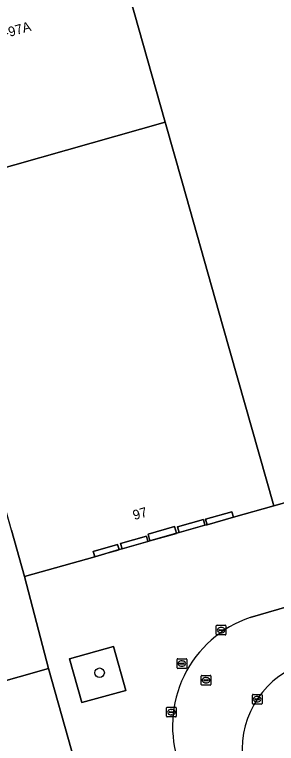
# Model space of a CAD drawing. Extents: x 159680 to 160786, y 387323 to 388340.
# Drawn here: x 159778.2 to 159805.3, y 388088.3 to 388163.8 of the extents above; entities that cross this region are included whole.
import ezdxf

# ---------------------------------------------------------------- set-up
doc = ezdxf.new("R2010")
doc.units = 0
for name, color, linetype in [('IMGEO_Boom', 7, 'Continuous'), ('IMGEO_Erf', 7, 'Continuous'), ('IMGEO_Groenvoorziening', 7, 'Continuous'), ('IMGEO_Kolk', 7, 'Continuous'), ('IMGEO_Pand', 7, 'Continuous'), ('IMGEO_Pand_nummerreeks', 7, 'Continuous'), ('IMGEO_Pand_overbouw', 7, 'Continuous'), ('IMGEO_Rijbaan_lokaal_gesloten', 7, 'Continuous'), ('IMGEO_Rioolput', 7, 'Continuous'), ('IMGEO_Voetpad_open', 7, 'Continuous')]:
    doc.layers.add(name, color=color, linetype=linetype)

msp = doc.modelspace()

# ---------------------------------------------------------------- linework, layer by layer
at = {"layer": 'IMGEO_Boom'}
msp.add_circle((159787.039, 388095.61), 0.489, dxfattribs=at)
at = {"layer": 'IMGEO_Erf'}
msp.add_lwpolyline([(159779.267, 388105.564), (159777.907, 388110.376), (159775.062, 388120.447), (159751.863, 388113.893), (159752.702, 388110.923), (159752.877, 388110.972), (159757.31, 388095.283), (159762.15, 388096.648), (159763.767, 388090.921), (159781.751, 388096.038)], close=True, dxfattribs=at)
at = {"layer": 'IMGEO_Groenvoorziening'}
msp.add_lwpolyline([(159788.459, 388098.325), (159783.926, 388097.046), (159785.198, 388092.511), (159789.733, 388093.783)], close=True, dxfattribs=at)
msp.add_arc((159811.11, 388087.728), 9.316, 111.33818, 189.99653, dxfattribs=at)
at = {"layer": 'IMGEO_Kolk'}
for p, q in [((159799.105, 388099.596), (159799.105, 388100.448)), ((159799.18, 388100.522), (159800.032, 388100.522)), ((159799.593, 388100.302), (159799.618, 388100.302)), ((159800.106, 388100.448), (159800.106, 388099.596)), ((159800.032, 388099.522), (159799.18, 388099.522)), ((159799.364, 388100.016), (159799.364, 388100.028)), ((159799.802, 388099.979), (159799.404, 388099.979)), ((159799.407, 388100.065), (159799.805, 388100.065)), ((159799.616, 388099.742), (159799.591, 388099.742)), ((159799.848, 388100.028), (159799.848, 388100.016)), ((159802.909, 388093.361), (159803.761, 388093.361)), ((159802.834, 388092.435), (159802.834, 388093.287)), ((159803.093, 388092.855), (159803.093, 388092.867)), ((159803.531, 388092.818), (159803.133, 388092.818)), ((159803.136, 388092.904), (159803.534, 388092.904)), ((159803.322, 388093.141), (159803.347, 388093.141)), ((159803.577, 388092.867), (159803.577, 388092.855)), ((159803.835, 388093.287), (159803.835, 388092.435)), ((159793.964, 388091.104), (159793.964, 388091.956)), ((159794.039, 388092.03), (159794.891, 388092.03)), ((159794.965, 388091.956), (159794.965, 388091.104)), ((159803.761, 388092.361), (159802.909, 388092.361)), ((159803.345, 388092.581), (159803.32, 388092.581)), ((159794.223, 388091.524), (159794.223, 388091.536)), ((159794.661, 388091.487), (159794.263, 388091.487)), ((159794.266, 388091.573), (159794.664, 388091.573)), ((159794.475, 388091.25), (159794.45, 388091.25)), ((159794.452, 388091.81), (159794.477, 388091.81)), ((159794.707, 388091.536), (159794.707, 388091.524)), ((159794.891, 388091.03), (159794.039, 388091.03))]:
    msp.add_line(p, q, dxfattribs=at)
for points in [[(159799.105, 388099.596), (159799.105, 388100.448)], [(159799.18, 388100.522), (159800.032, 388100.522)], [(159800.106, 388100.448), (159800.106, 388099.596)], [(159800.032, 388099.522), (159799.18, 388099.522)], [(159802.909, 388093.361), (159803.761, 388093.361)], [(159802.834, 388092.435), (159802.834, 388093.287)], [(159803.835, 388093.287), (159803.835, 388092.435)], [(159793.964, 388091.104), (159793.964, 388091.956)], [(159794.039, 388092.03), (159794.891, 388092.03)], [(159794.965, 388091.956), (159794.965, 388091.104)], [(159803.761, 388092.361), (159802.909, 388092.361)], [(159794.891, 388091.03), (159794.039, 388091.03)]]:
    msp.add_lwpolyline(points, dxfattribs=at)
for centre, radius, start, end in [((159799.182, 388100.446), 0.0765, 91.55205, 178.44795), ((159799.182, 388100.446), 0.0765, 91.55205, 178.44795), ((159800.03, 388100.446), 0.0765, 1.55205, 88.44795), ((159800.03, 388100.446), 0.0765, 1.55205, 88.44795), ((159799.182, 388099.598), 0.0765, 181.55205, 268.44795), ((159799.182, 388099.598), 0.0765, 181.55205, 268.44795), ((159799.404, 388100.025), 0.0403, 85.87752, 175.75265), ((159799.401, 388100.015), 0.0366, 178.93798, 274.71019), ((159799.805, 388100.022), 0.043, 264.86636, 352.45326), ((159799.809, 388100.027), 0.0386, 1.73085, 96.63898), ((159800.03, 388099.598), 0.0765, 271.55205, 358.44795), ((159800.03, 388099.598), 0.0765, 271.55205, 358.44795), ((159802.911, 388093.285), 0.0765, 91.55205, 178.44795), ((159802.911, 388093.285), 0.0765, 91.55205, 178.44795), ((159803.759, 388093.285), 0.0765, 1.55205, 88.44795), ((159803.759, 388093.285), 0.0765, 1.55205, 88.44795), ((159803.133, 388092.864), 0.0403, 85.87752, 175.75265), ((159803.13, 388092.854), 0.0366, 178.93798, 274.71019), ((159803.534, 388092.861), 0.043, 264.86636, 352.45326), ((159803.538, 388092.866), 0.0386, 1.73085, 96.63898), ((159794.041, 388091.954), 0.0765, 91.55205, 178.44795), ((159794.041, 388091.954), 0.0765, 91.55205, 178.44795), ((159794.889, 388091.954), 0.0765, 1.55205, 88.44795), ((159794.889, 388091.954), 0.0765, 1.55205, 88.44795), ((159802.911, 388092.437), 0.0765, 181.55205, 268.44795), ((159802.911, 388092.437), 0.0765, 181.55205, 268.44795), ((159803.759, 388092.437), 0.0765, 271.55205, 358.44795), ((159803.759, 388092.437), 0.0765, 271.55205, 358.44795), ((159794.041, 388091.106), 0.0765, 181.55205, 268.44795), ((159794.041, 388091.106), 0.0765, 181.55205, 268.44795), ((159794.263, 388091.533), 0.0403, 85.87752, 175.75265), ((159794.26, 388091.523), 0.0366, 178.93798, 274.71019), ((159794.664, 388091.53), 0.043, 264.86636, 352.45326), ((159794.668, 388091.535), 0.0386, 1.73085, 96.63898), ((159794.889, 388091.106), 0.0765, 271.55205, 358.44795), ((159794.889, 388091.106), 0.0765, 271.55205, 358.44795)]:
    msp.add_arc(centre, radius, start, end, dxfattribs=at)
for centre, major_axis, ratio, start_param, end_param in [((159799.592, 388100.022), (-0.387, 0.002), 0.722429, 4.712389, 7.853982), ((159799.617, 388100.022), (-0.39, 0.002), 0.717154, 1.570796, 4.712389), ((159803.321, 388092.861), (-0.387, 0.002), 0.722429, 4.712389, 7.853982), ((159803.346, 388092.861), (-0.39, 0.002), 0.717154, 1.570796, 4.712389), ((159794.451, 388091.53), (-0.387, 0.002), 0.722429, 4.712389, 7.853982), ((159794.476, 388091.53), (-0.39, 0.002), 0.717154, 1.570796, 4.712389)]:
    msp.add_ellipse(centre, major_axis=major_axis, ratio=ratio, start_param=start_param, end_param=end_param, dxfattribs=at)
at = {"layer": 'IMGEO_Pand'}
for points in [[(159814.275, 388172.417), (159790.158, 388165.594), (159793.826, 388152.611), (159795.605, 388146.314), (159799.791, 388131.499), (159805.048, 388112.894), (159820.275, 388117.209), (159829.165, 388119.728), (159823.152, 388141.005), (159819.726, 388153.128)], [(159784.499, 388086.298), (159784.445, 388086.491), (159781.751, 388096.038), (159763.767, 388090.921), (159758.926, 388089.554), (159730.739, 388081.596), (159732.805, 388074.281), (159735.657, 388072.752), (159735.225, 388072.625), (159735.46, 388071.829), (159736.131, 388072.027), (159737.088, 388068.775), (159736.417, 388068.577), (159736.648, 388067.79), (159737.08, 388067.917), (159735.39, 388064.982), (159737.57, 388057.575), (159788.562, 388071.895), (159788.547, 388071.951)]]:
    msp.add_lwpolyline(points, close=True, dxfattribs=at)
for points in [[(159768.044, 388145.288), (159793.826, 388152.611), (159790.158, 388165.594), (159789.216, 388168.927), (159788.863, 388168.828), (159789.024, 388168.257), (159786.274, 388167.48), (159786.113, 388168.051), (159785.867, 388167.981), (159786.025, 388167.421), (159783.057, 388166.583), (159782.904, 388167.124), (159782.674, 388167.059), (159782.835, 388166.489), (159779.838, 388165.642), (159779.678, 388166.209), (159779.395, 388166.129), (159779.606, 388165.382), (159776.681, 388164.555)], [(159777.907, 388110.376), (159779.267, 388105.564), (159786.531, 388107.616), (159786.376, 388108.167), (159788.9, 388108.88), (159789.049, 388108.35), (159789.361, 388108.439), (159789.206, 388108.986), (159791.878, 388109.741), (159792.024, 388109.182), (159792.248, 388109.25), (159792.073, 388109.959), (159794.792, 388110.736), (159794.973, 388110.054), (159795.255, 388110.134), (159795.092, 388110.712), (159797.767, 388111.467), (159797.936, 388110.87), (159798.164, 388110.935), (159798.001, 388111.512), (159800.717, 388112.279), (159800.877, 388111.712), (159805.048, 388112.894), (159799.791, 388131.499), (159795.605, 388146.314), (159793.826, 388152.611), (159768.044, 388145.288)]]:
    msp.add_lwpolyline(points, dxfattribs=at)
at = {"layer": 'IMGEO_Pand_overbouw'}
for points in [[(159800.877, 388111.712), (159800.717, 388112.279), (159798.001, 388111.512), (159798.164, 388110.937)], [(159795.255, 388110.134), (159795.261, 388110.111), (159797.935, 388110.872), (159797.767, 388111.467), (159795.092, 388110.712)], [(159794.979, 388110.031), (159794.973, 388110.054), (159794.792, 388110.736), (159792.073, 388109.959), (159792.247, 388109.254)], [(159789.361, 388108.439), (159789.362, 388108.434), (159792.022, 388109.19), (159791.878, 388109.741), (159789.206, 388108.986)], [(159789.05, 388108.346), (159789.049, 388108.35), (159788.9, 388108.88), (159786.376, 388108.167), (159786.528, 388107.628)]]:
    msp.add_lwpolyline(points, close=True, dxfattribs=at)
at = {"layer": 'IMGEO_Rijbaan_lokaal_gesloten'}
msp.add_lwpolyline([(159868.94, 388120.232), (159867.733, 388119.871), (159866.069, 388119.418), (159846.773, 388113.929), (159836.895, 388111.119), (159817.68, 388105.652), (159807.454, 388102.743), (159802.605, 388101.325)], dxfattribs=at)
for centre, radius, start, end in [((159806.452, 388090.092), 11.873, 108.90437, 199.38793), ((159811.11, 388087.728), 9.316, 111.33818, 189.99653)]:
    msp.add_arc(centre, radius, start, end, dxfattribs=at)
at = {"layer": 'IMGEO_Rioolput'}
for p, q in [((159795.048, 388096.126), (159795.048, 388096.978)), ((159795.123, 388097.052), (159795.975, 388097.052)), ((159795.307, 388096.546), (159795.307, 388096.558)), ((159795.745, 388096.509), (159795.347, 388096.509)), ((159795.35, 388096.595), (159795.748, 388096.595)), ((159795.536, 388096.832), (159795.561, 388096.832)), ((159795.791, 388096.558), (159795.791, 388096.546)), ((159796.049, 388096.978), (159796.049, 388096.126)), ((159795.975, 388096.052), (159795.123, 388096.052)), ((159795.559, 388096.272), (159795.534, 388096.272)), ((159797.546, 388094.4), (159797.546, 388095.252)), ((159797.621, 388095.326), (159798.473, 388095.326)), ((159797.848, 388094.869), (159798.246, 388094.869)), ((159798.034, 388095.106), (159798.059, 388095.106)), ((159798.547, 388095.252), (159798.547, 388094.4)), ((159798.473, 388094.326), (159797.621, 388094.326)), ((159797.805, 388094.82), (159797.805, 388094.832)), ((159798.243, 388094.783), (159797.845, 388094.783)), ((159798.057, 388094.546), (159798.032, 388094.546)), ((159798.289, 388094.832), (159798.289, 388094.82))]:
    msp.add_line(p, q, dxfattribs=at)
for points in [[(159795.048, 388096.126), (159795.048, 388096.978)], [(159795.123, 388097.052), (159795.975, 388097.052)], [(159796.049, 388096.978), (159796.049, 388096.126)], [(159795.975, 388096.052), (159795.123, 388096.052)], [(159797.546, 388094.4), (159797.546, 388095.252)], [(159797.621, 388095.326), (159798.473, 388095.326)], [(159798.547, 388095.252), (159798.547, 388094.4)], [(159798.473, 388094.326), (159797.621, 388094.326)]]:
    msp.add_lwpolyline(points, dxfattribs=at)
for centre, radius, start, end in [((159795.125, 388096.976), 0.0765, 91.55205, 178.44795), ((159795.125, 388096.976), 0.0765, 91.55205, 178.44795), ((159795.347, 388096.555), 0.0403, 85.87752, 175.75265), ((159795.344, 388096.545), 0.0366, 178.93798, 274.71019), ((159795.748, 388096.552), 0.043, 264.86636, 352.45326), ((159795.752, 388096.557), 0.0386, 1.73085, 96.63898), ((159795.973, 388096.976), 0.0765, 1.55205, 88.44795), ((159795.973, 388096.976), 0.0765, 1.55205, 88.44795), ((159795.125, 388096.128), 0.0765, 181.55205, 268.44795), ((159795.125, 388096.128), 0.0765, 181.55205, 268.44795), ((159795.973, 388096.128), 0.0765, 271.55205, 358.44795), ((159795.973, 388096.128), 0.0765, 271.55205, 358.44795), ((159797.623, 388095.25), 0.0765, 91.55205, 178.44795), ((159797.623, 388095.25), 0.0765, 91.55205, 178.44795), ((159797.845, 388094.829), 0.0403, 85.87752, 175.75265), ((159798.25, 388094.831), 0.0386, 1.73085, 96.63898), ((159798.471, 388095.25), 0.0765, 1.55205, 88.44795), ((159798.471, 388095.25), 0.0765, 1.55205, 88.44795), ((159797.623, 388094.402), 0.0765, 181.55205, 268.44795), ((159797.623, 388094.402), 0.0765, 181.55205, 268.44795), ((159797.842, 388094.819), 0.0366, 178.93798, 274.71019), ((159798.246, 388094.826), 0.043, 264.86636, 352.45326), ((159798.471, 388094.402), 0.0765, 271.55205, 358.44795), ((159798.471, 388094.402), 0.0765, 271.55205, 358.44795)]:
    msp.add_arc(centre, radius, start, end, dxfattribs=at)
for centre, major_axis, ratio, start_param, end_param in [((159795.535, 388096.552), (-0.387, 0.002), 0.722429, 4.712389, 7.853982), ((159795.56, 388096.552), (-0.39, 0.002), 0.717154, 1.570796, 4.712389), ((159798.033, 388094.826), (-0.387, 0.002), 0.722429, 4.712389, 7.853982), ((159798.058, 388094.826), (-0.39, 0.002), 0.717154, 1.570796, 4.712389)]:
    msp.add_ellipse(centre, major_axis=major_axis, ratio=ratio, start_param=start_param, end_param=end_param, dxfattribs=at)
at = {"layer": 'IMGEO_Voetpad_open'}
for points in [[(159862.486, 388129.241), (159856.524, 388127.56), (159845.753, 388124.456), (159839.88, 388122.764), (159834.552, 388121.254), (159829.165, 388119.728), (159820.275, 388117.209), (159805.048, 388112.894), (159800.877, 388111.712), (159798.164, 388110.935), (159797.936, 388110.87), (159795.255, 388110.134), (159794.973, 388110.054), (159792.248, 388109.25), (159792.024, 388109.182), (159789.361, 388108.439), (159789.049, 388108.35), (159786.531, 388107.616), (159779.267, 388105.564), (159781.751, 388096.038), (159784.445, 388086.491)], [(159802.605, 388101.325), (159807.454, 388102.743)]]:
    msp.add_lwpolyline(points, dxfattribs=at)
for points in [[(159800.877, 388111.712), (159800.717, 388112.279), (159798.001, 388111.512), (159798.164, 388110.935)], [(159797.936, 388110.87), (159797.767, 388111.467), (159795.092, 388110.712), (159795.255, 388110.134)], [(159794.973, 388110.054), (159794.792, 388110.736), (159792.073, 388109.959), (159792.248, 388109.25)], [(159792.024, 388109.182), (159791.878, 388109.741), (159789.206, 388108.986), (159789.361, 388108.439)], [(159789.049, 388108.35), (159788.9, 388108.88), (159786.376, 388108.167), (159786.531, 388107.616)], [(159789.733, 388093.783), (159785.198, 388092.511), (159783.926, 388097.046), (159788.459, 388098.325)]]:
    msp.add_lwpolyline(points, close=True, dxfattribs=at)
msp.add_arc((159806.452, 388090.092), 11.873, 108.90437, 199.38793, dxfattribs=at)

# ---------------------------------------------------------------- texts
at = {"layer": 'IMGEO_Pand_nummerreeks'}
for s, rotation, p in [('97-97A', 15.78746, (159775.881, 388160.92)), ('97', 15.84222, (159790.627, 388111.41))]:
    msp.add_text(s, height=1, rotation=rotation, dxfattribs=at).set_placement(p)

doc.saveas('drawing.dxf')
